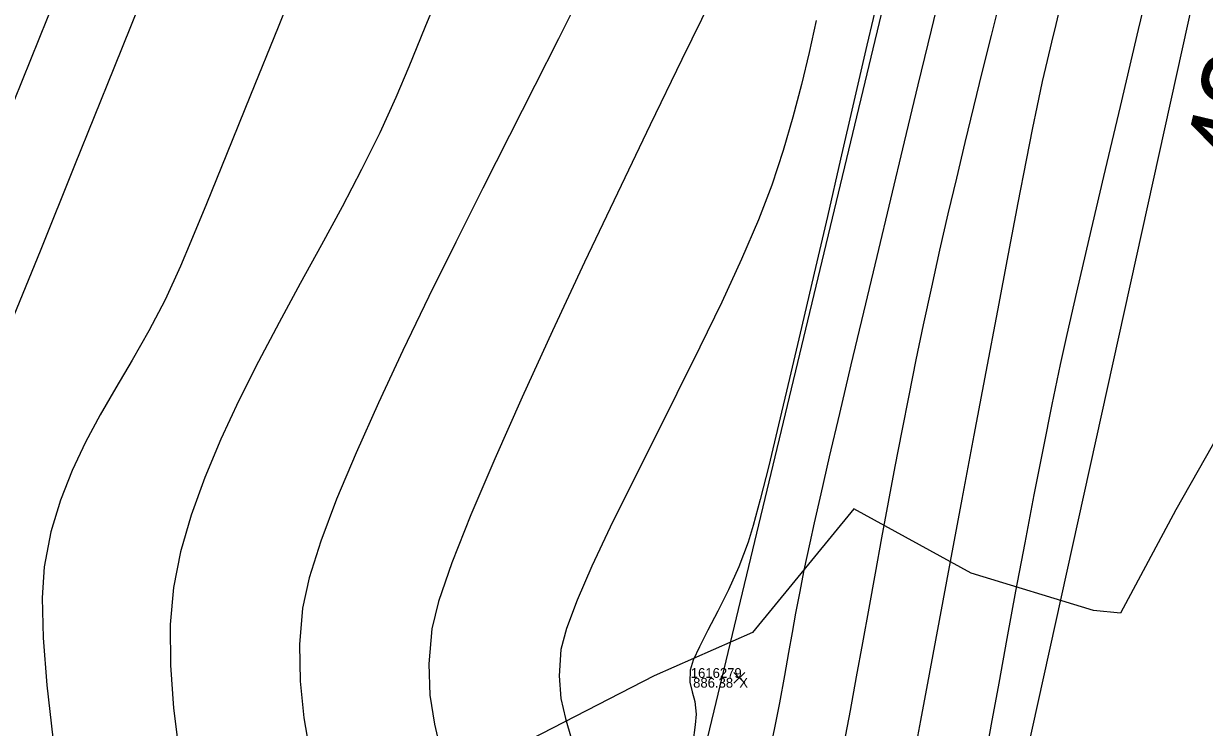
# Model space of a CAD drawing. Extents: x 1957117 to 1971063, y 701601 to 715861.
# Drawn here: x 1963296.75 to 1963339.04, y 706110.73 to 706135.93 of the extents above; entities that cross this region are included whole.
import ezdxf

# ---------------------------------------------------------------- set-up
doc = ezdxf.new("R2010")
doc.units = 0
for name, color, linetype in [('AP_X_Lights', 7, 'Continuous'), ('DT_X_Break_Line', 7, 'Continuous'), ('DT_X_Contour_Major', 7, 'Continuous'), ('DT_X_Contour_Minor', 7, 'Continuous'), ('GE_X_CL_20', 7, 'Continuous'), ('HY_X_Water_Edge', 7, 'Continuous'), ('PV_P_Shoulder', 7, 'Continuous'), ('RS_Raster1', 7, 'Continuous'), ('RW_X_Esmt_RR', 7, 'Continuous'), ('SC_Scratch1', 7, 'Continuous'), ('SC_Shading5', 7, 'Continuous'), ('VG_X_Tree_Line_Rt', 7, 'Continuous')]:
    doc.layers.add(name, color=color, linetype=linetype)

msp = doc.modelspace()

# ---------------------------------------------------------------- linework, layer by layer
at = {"layer": 'AP_X_Lights'}
for p, q in [((1963322.188, 706112.307), (1963322.576, 706112.697)), ((1963322.188, 706112.697), (1963322.576, 706112.307))]:
    msp.add_line(p, q, dxfattribs=at)
at = {"layer": 'DT_X_Break_Line'}
for points in [[(1963218.329, 705756.178), (1963229.265, 705808.356), (1963234.8, 705853.147), (1963240.079, 705903.468), (1963258.033, 705954.684), (1963270.287, 705999.321), (1963276.323, 706049.345), (1963291.502, 706096.678), (1963290.138, 706117.655), (1963319.921, 706191.295), (1963330.374, 706242.631), (1963344.413, 706289.409), (1963345.772, 706340.009), (1963383.117, 706434.704), (1963392.11, 706487.426), (1963408.164, 706535.687), (1963423.633, 706582.721), (1963435.242, 706630.63), (1963443.084, 706680.696), (1963464.732, 706726.815), (1963480.654, 706774.214), (1963508.465, 706799.669), (1963511.002, 706809.48)], [(1963248.355, 705747.376), (1963261.829, 705795.923), (1963267.581, 705840.559), (1963287.153, 705892.264), (1963291.083, 705944.763), (1963301.574, 705996.211), (1963311.528, 706039.027), (1963334.717, 706086.75), (1963331.957, 706106.508), (1963348.786, 706182.796), (1963365.664, 706223.934), (1963373.462, 706281.461), (1963387.853, 706330.217), (1963397.264, 706379.501), (1963407.696, 706427.592), (1963426.755, 706477.16), (1963442.136, 706524.014), (1963446.007, 706569.971), (1963489.391, 706666.839), (1963500.526, 706701.536)]]:
    msp.add_lwpolyline(points, dxfattribs=at)
at = {"layer": 'DT_X_Contour_Major'}
for points in [[(1963315.156, 706172.002), (1963313.61, 706168.163), (1963311.958, 706164.061), (1963310.231, 706159.772), (1963308.459, 706155.371), (1963306.672, 706150.935), (1963304.901, 706146.537), (1963303.176, 706142.255), (1963301.527, 706138.163), (1963299.985, 706134.338), (1963298.58, 706130.854), (1963297.343, 706127.788), (1963296.303, 706125.215)], [(1963315.156, 706172.002), (1963313.61, 706168.163), (1963311.958, 706164.061), (1963310.231, 706159.772), (1963308.459, 706155.371), (1963306.672, 706150.935), (1963304.901, 706146.537), (1963303.176, 706142.255), (1963301.527, 706138.163), (1963299.985, 706134.338), (1963298.58, 706130.854), (1963297.343, 706127.788), (1963296.303, 706125.215)], [(1963339.599, 706147.972), (1963338.843, 706144.823), (1963338.095, 706141.696), (1963337.366, 706138.643), (1963336.669, 706135.717), (1963336.017, 706132.969), (1963335.423, 706130.451), (1963334.898, 706128.215), (1963334.457, 706126.313), (1963334.11, 706124.797), (1963333.872, 706123.719), (1963333.574, 706122.296), (1963333.259, 706120.726), (1963332.933, 706119.057), (1963332.603, 706117.334), (1963332.278, 706115.605), (1963331.965, 706113.916), (1963331.671, 706112.315), (1963331.403, 706110.848), (1963331.17, 706109.563)], [(1963339.599, 706147.972), (1963338.843, 706144.823), (1963338.095, 706141.696), (1963337.366, 706138.643), (1963336.669, 706135.717), (1963336.017, 706132.969), (1963335.423, 706130.451), (1963334.898, 706128.215), (1963334.457, 706126.313), (1963334.11, 706124.797), (1963333.872, 706123.719), (1963333.574, 706122.296), (1963333.259, 706120.726), (1963332.933, 706119.057), (1963332.603, 706117.334), (1963332.278, 706115.605), (1963331.965, 706113.916), (1963331.671, 706112.315), (1963331.403, 706110.848), (1963331.17, 706109.563)], [(1963325.13, 706136.041), (1963324.879, 706134.9), (1963324.604, 706133.749), (1963324.296, 706132.58), (1963323.947, 706131.383), (1963323.546, 706130.151), (1963323.073, 706128.905), (1963322.465, 706127.493), (1963321.753, 706125.957), (1963320.969, 706124.34), (1963320.146, 706122.683), (1963319.316, 706121.029), (1963318.511, 706119.419), (1963317.764, 706117.897), (1963317.107, 706116.504), (1963316.572, 706115.282), (1963316.191, 706114.274), (1963315.997, 706113.522), (1963315.928, 706112.57), (1963315.997, 706111.764), (1963316.158, 706111.043), (1963316.362, 706110.347)], [(1963325.13, 706136.041), (1963324.879, 706134.9), (1963324.604, 706133.749), (1963324.296, 706132.58), (1963323.947, 706131.383), (1963323.546, 706130.151), (1963323.073, 706128.905), (1963322.465, 706127.493), (1963321.753, 706125.957), (1963320.969, 706124.34), (1963320.146, 706122.683), (1963319.316, 706121.029), (1963318.511, 706119.419), (1963317.764, 706117.897), (1963317.107, 706116.504), (1963316.572, 706115.282), (1963316.191, 706114.274), (1963315.997, 706113.522), (1963315.928, 706112.57), (1963315.997, 706111.764), (1963316.158, 706111.043), (1963316.362, 706110.347)]]:
    msp.add_lwpolyline(points, dxfattribs=at)
at = {"layer": 'DT_X_Contour_Minor'}
for points in [[(1963306.958, 706138.508), (1963305.869, 706135.808), (1963304.883, 706133.368), (1963304.02, 706131.24), (1963303.301, 706129.476), (1963302.747, 706128.127), (1963302.377, 706127.245), (1963301.819, 706126.037), (1963301.237, 706124.926), (1963300.647, 706123.885), (1963300.062, 706122.891), (1963299.498, 706121.917), (1963298.968, 706120.939), (1963298.488, 706119.931), (1963298.072, 706118.869), (1963297.734, 706117.727), (1963297.49, 706116.48), (1963297.415, 706115.366), (1963297.454, 706113.932), (1963297.59, 706112.24), (1963297.804, 706110.352)], [(1963306.958, 706138.508), (1963305.869, 706135.808), (1963304.883, 706133.368), (1963304.02, 706131.24), (1963303.301, 706129.476), (1963302.747, 706128.127), (1963302.377, 706127.245), (1963301.819, 706126.037), (1963301.237, 706124.926), (1963300.647, 706123.885), (1963300.062, 706122.891), (1963299.498, 706121.917), (1963298.968, 706120.939), (1963298.488, 706119.931), (1963298.072, 706118.869), (1963297.734, 706117.727), (1963297.49, 706116.48), (1963297.415, 706115.366), (1963297.454, 706113.932), (1963297.59, 706112.24), (1963297.804, 706110.352)], [(1963311.803, 706137.443), (1963311.127, 706135.79), (1963310.547, 706134.388), (1963310.079, 706133.28), (1963309.505, 706132.016), (1963308.858, 706130.711), (1963308.157, 706129.373), (1963307.42, 706128.008), (1963306.663, 706126.625), (1963305.907, 706125.229), (1963305.168, 706123.829), (1963304.465, 706122.432), (1963303.816, 706121.045), (1963303.238, 706119.675), (1963302.75, 706118.329), (1963302.371, 706117.016), (1963302.117, 706115.741), (1963302.001, 706114.414), (1963302.009, 706112.962), (1963302.122, 706111.414), (1963302.319, 706109.803)], [(1963311.803, 706137.443), (1963311.127, 706135.79), (1963310.547, 706134.388), (1963310.079, 706133.28), (1963309.505, 706132.016), (1963308.858, 706130.711), (1963308.157, 706129.373), (1963307.42, 706128.008), (1963306.663, 706126.625), (1963305.907, 706125.229), (1963305.168, 706123.829), (1963304.465, 706122.432), (1963303.816, 706121.045), (1963303.238, 706119.675), (1963302.75, 706118.329), (1963302.371, 706117.016), (1963302.117, 706115.741), (1963302.001, 706114.414), (1963302.009, 706112.962), (1963302.122, 706111.414), (1963302.319, 706109.803)], [(1963329.697, 706137.54), (1963329.25, 706135.697), (1963328.776, 706133.736), (1963328.286, 706131.703), (1963327.792, 706129.639), (1963327.302, 706127.59), (1963326.828, 706125.6), (1963326.38, 706123.711), (1963325.969, 706121.969), (1963325.605, 706120.417), (1963325.299, 706119.098), (1963325.062, 706118.058), (1963324.903, 706117.34), (1963324.697, 706116.358), (1963324.535, 706115.54), (1963324.4, 706114.82), (1963324.276, 706114.133), (1963324.148, 706113.412), (1963324, 706112.591), (1963323.816, 706111.605), (1963323.651, 706110.777), (1963323.411, 706109.613)], [(1963329.697, 706137.54), (1963329.25, 706135.697), (1963328.776, 706133.736), (1963328.286, 706131.703), (1963327.792, 706129.639), (1963327.302, 706127.59), (1963326.828, 706125.6), (1963326.38, 706123.711), (1963325.969, 706121.969), (1963325.605, 706120.417), (1963325.299, 706119.098), (1963325.062, 706118.058), (1963324.903, 706117.34), (1963324.697, 706116.358), (1963324.535, 706115.54), (1963324.4, 706114.82), (1963324.276, 706114.133), (1963324.148, 706113.412), (1963324, 706112.591), (1963323.816, 706111.605), (1963323.651, 706110.777), (1963323.411, 706109.613)], [(1963316.655, 706136.901), (1963315.905, 706135.388), (1963315.064, 706133.717), (1963314.155, 706131.923), (1963313.204, 706130.042), (1963312.234, 706128.109), (1963311.27, 706126.159), (1963310.336, 706124.228), (1963309.458, 706122.351), (1963308.658, 706120.562), (1963307.963, 706118.897), (1963307.396, 706117.392), (1963306.981, 706116.082), (1963306.743, 706115.001), (1963306.63, 706113.696), (1963306.655, 706112.384), (1963306.791, 706111.07), (1963307.011, 706109.758)], [(1963316.655, 706136.901), (1963315.905, 706135.388), (1963315.064, 706133.717), (1963314.155, 706131.923), (1963313.204, 706130.042), (1963312.234, 706128.109), (1963311.27, 706126.159), (1963310.336, 706124.228), (1963309.458, 706122.351), (1963308.658, 706120.562), (1963307.963, 706118.897), (1963307.396, 706117.392), (1963306.981, 706116.082), (1963306.743, 706115.001), (1963306.63, 706113.696), (1963306.655, 706112.384), (1963306.791, 706111.07), (1963307.011, 706109.758)], [(1963327.403, 706137.086), (1963326.954, 706135.157), (1963326.487, 706133.142), (1963326.011, 706131.082), (1963325.535, 706129.019), (1963325.066, 706126.993), (1963324.613, 706125.047), (1963324.184, 706123.222), (1963323.788, 706121.559), (1963323.434, 706120.101), (1963323.129, 706118.887), (1963322.883, 706117.96), (1963322.702, 706117.362), (1963322.366, 706116.481), (1963321.993, 706115.652), (1963321.613, 706114.889), (1963321.257, 706114.205), (1963320.953, 706113.617), (1963320.732, 706113.138), (1963320.624, 706112.783), (1963320.616, 706112.351), (1963320.696, 706112.005), (1963320.792, 706111.653), (1963320.835, 706111.206), (1963320.804, 706110.826), (1963320.721, 706110.178)], [(1963327.403, 706137.086), (1963326.954, 706135.157), (1963326.487, 706133.142), (1963326.011, 706131.082), (1963325.535, 706129.019), (1963325.066, 706126.993), (1963324.613, 706125.047), (1963324.184, 706123.222), (1963323.788, 706121.559), (1963323.434, 706120.101), (1963323.129, 706118.887), (1963322.883, 706117.96), (1963322.702, 706117.362), (1963322.366, 706116.481), (1963321.993, 706115.652), (1963321.613, 706114.889), (1963321.257, 706114.205), (1963320.953, 706113.617), (1963320.732, 706113.138), (1963320.624, 706112.783), (1963320.616, 706112.351), (1963320.696, 706112.005), (1963320.792, 706111.653), (1963320.835, 706111.206), (1963320.804, 706110.826), (1963320.721, 706110.178)], [(1963321.392, 706136.813), (1963320.33, 706134.642), (1963319.194, 706132.304), (1963318.019, 706129.864), (1963316.84, 706127.383), (1963315.692, 706124.927), (1963314.608, 706122.559), (1963313.623, 706120.342), (1963312.772, 706118.34), (1963312.09, 706116.617), (1963311.611, 706115.236), (1963311.37, 706114.262), (1963311.262, 706113.006), (1963311.305, 706111.881), (1963311.462, 706110.847), (1963311.696, 706109.866)], [(1963321.392, 706136.813), (1963320.33, 706134.642), (1963319.194, 706132.304), (1963318.019, 706129.864), (1963316.84, 706127.383), (1963315.692, 706124.927), (1963314.608, 706122.559), (1963313.623, 706120.342), (1963312.772, 706118.34), (1963312.09, 706116.617), (1963311.611, 706115.236), (1963311.37, 706114.262), (1963311.262, 706113.006), (1963311.305, 706111.881), (1963311.462, 706110.847), (1963311.696, 706109.866)], [(1963331.722, 706136.802), (1963331.4, 706135.507), (1963331.083, 706134.224), (1963330.77, 706132.949), (1963330.461, 706131.677), (1963330.156, 706130.4), (1963329.855, 706129.114), (1963329.556, 706127.813), (1963329.261, 706126.491), (1963328.968, 706125.142), (1963328.705, 706123.886), (1963328.448, 706122.619), (1963328.198, 706121.345), (1963327.953, 706120.068), (1963327.714, 706118.791), (1963327.479, 706117.518), (1963327.248, 706116.252), (1963327.02, 706114.997), (1963326.795, 706113.757), (1963326.572, 706112.534), (1963326.349, 706111.333), (1963326.128, 706110.157)], [(1963331.722, 706136.802), (1963331.4, 706135.507), (1963331.083, 706134.224), (1963330.77, 706132.949), (1963330.461, 706131.677), (1963330.156, 706130.4), (1963329.855, 706129.114), (1963329.556, 706127.813), (1963329.261, 706126.491), (1963328.968, 706125.142), (1963328.705, 706123.886), (1963328.448, 706122.619), (1963328.198, 706121.345), (1963327.953, 706120.068), (1963327.714, 706118.791), (1963327.479, 706117.518), (1963327.248, 706116.252), (1963327.02, 706114.997), (1963326.795, 706113.757), (1963326.572, 706112.534), (1963326.349, 706111.333), (1963326.128, 706110.157)], [(1963333.877, 706136.562), (1963333.712, 706135.902), (1963333.558, 706135.272), (1963333.402, 706134.61), (1963333.231, 706133.855), (1963333.034, 706132.945), (1963332.883, 706132.204), (1963332.654, 706131.036), (1963332.36, 706129.509), (1963332.014, 706127.692), (1963331.627, 706125.653), (1963331.213, 706123.463), (1963330.785, 706121.189), (1963330.355, 706118.9), (1963329.935, 706116.665), (1963329.539, 706114.553), (1963329.179, 706112.633), (1963328.867, 706110.973), (1963328.617, 706109.642)], [(1963333.877, 706136.562), (1963333.712, 706135.902), (1963333.558, 706135.272), (1963333.402, 706134.61), (1963333.231, 706133.855), (1963333.034, 706132.945), (1963332.883, 706132.204), (1963332.654, 706131.036), (1963332.36, 706129.509), (1963332.014, 706127.692), (1963331.627, 706125.653), (1963331.213, 706123.463), (1963330.785, 706121.189), (1963330.355, 706118.9), (1963329.935, 706116.665), (1963329.539, 706114.553), (1963329.179, 706112.633), (1963328.867, 706110.973), (1963328.617, 706109.642)]]:
    msp.add_lwpolyline(points, dxfattribs=at)
at = {"layer": 'HY_X_Water_Edge'}
msp.add_spline([(1963191.723, 701994.048), (1963062.047, 702441.167), (1962863.491, 703169.356), (1962827.53, 703438.691), (1962823.213, 703537.412), (1962817.962, 703593.874), (1962817.97, 703697.316), (1962828.582, 703804.235), (1962836.461, 703844.734), (1962850.687, 703896.004), (1962867.251, 703938.846), (1962873.848, 703992.355), (1962884.135, 704091.371), (1962891.241, 704140.854), (1962897.382, 704180.529), (1962905.467, 704230.979), (1962943.949, 704328.022), (1962948.537, 704378.842), (1962964.114, 704426.264), (1963004.885, 704570.73), (1963042.054, 704716.522), (1963062.038, 704814.417), (1963072.171, 704860.237), (1963090.023, 704956.798), (1963107.066, 705031.783), (1963133.773, 705105.742), (1963148.685, 705206.74), (1963175.48, 705301.059), (1963191.635, 705353.417), (1963210.988, 705447.286), (1963219.532, 705497.27), (1963230.124, 705549.475), (1963251.052, 705591.159), (1963275.289, 705693.429), (1963292.982, 705784.032), (1963302.841, 705839.645), (1963335.126, 705936.766), (1963359.752, 706046.75), (1963389.133, 706177.299), (1963417.827, 706273.456), (1963475.868, 706451.902), (1963533.782, 706640.53), (1963553.86, 706696.984), (1963580.184, 706715.425), (1963609.172, 706718.73), (1963617.062, 706714.691), (1963619.447, 706694.678), (1963564.282, 706533.07), (1963531.853, 706395.229), (1963434.4, 706006.96), (1963354.09, 705679.186), (1963237.513, 705206.07), (1963167.369, 704892.962), (1963059.145, 704434.176), (1962907.914, 703908.742), (1962877.458, 703703.326), (1962898.357, 703412.121), (1962942.65, 703052.267), (1963048.963, 702674.866), (1963191.468, 702189.666), (1963245.396, 702019.832)], degree=3, dxfattribs=at)
at = {"layer": 'RW_X_Esmt_RR'}
msp.add_lwpolyline([(1962866.45, 704268.068), (1963123.345, 705337.727), (1963135.496, 705336.937), (1963400.797, 706441.601)], dxfattribs=at)
at = {"layer": 'SC_Shading5'}
for points in [[(1963026.912, 704294.121), (1963138.818, 704737.794), (1963251.679, 705213.963), (1963374.306, 705730.111), (1963454.783, 706045.593), (1963517.244, 706296.713), (1963562.763, 706479.256), (1963580.13, 706553.799), (1963589.678, 706586.994)], [(1963609.915, 706579.703), (1963587.283, 706499.153), (1963552.056, 706354.005), (1963480.911, 706069.234), (1963357.401, 705576.869), (1963272.751, 705226.931), (1963210.247, 704956.481), (1963044.97, 704288.881)]]:
    msp.add_spline(points, degree=3, dxfattribs=at)
at = {"layer": 'VG_X_Tree_Line_Rt'}
msp.add_lwpolyline([(1963342.257, 706126.006), (1963338.014, 706118.518), (1963336.033, 706114.816), (1963335.069, 706114.913), (1963330.682, 706116.249), (1963326.479, 706118.552), (1963322.853, 706114.132), (1963319.336, 706112.573), (1963312.053, 706108.824)], dxfattribs=at)

# ---------------------------------------------------------------- texts
at = {"layer": 'GE_X_CL_20'}
msp.add_text('42', height=2.8, rotation=76.4953, dxfattribs=at).set_placement((1963340.98, 706130.44))
at = {"layer": 'PV_P_Shoulder'}
msp.add_text('886.38', height=0.35, dxfattribs=at).set_placement((1963320.729, 706112.152))
at = {"layer": 'RS_Raster1'}
msp.add_text('1616279', height=0.35, dxfattribs=at).set_placement((1963320.646, 706112.502))
at = {"layer": 'SC_Scratch1'}
msp.add_text('X', height=0.35, dxfattribs=at).set_placement((1963322.382, 706112.152))

doc.saveas('drawing.dxf')
